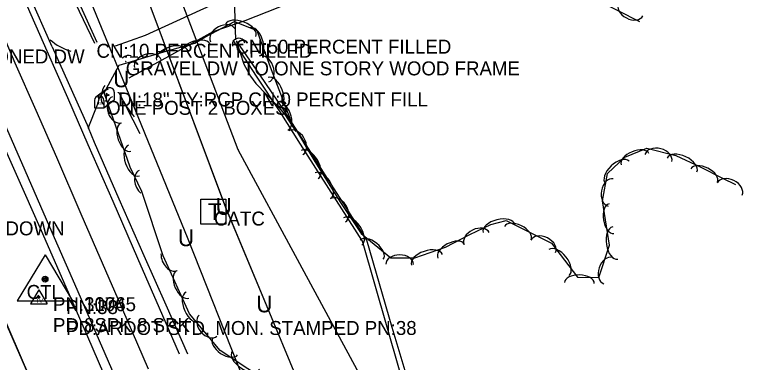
# Model space of a CAD drawing. Extents: x 954793 to 988390, y 1867850 to 1924428.
# Drawn here: x 964997.6 to 965258.9, y 1899641 to 1899765.7 of the extents above; entities that cross this region are included whole.
import ezdxf

# ---------------------------------------------------------------- set-up
doc = ezdxf.new("R2010")
doc.units = 0
for name, color, linetype in [('Default', 7, 'Continuous'), ('S_CROSS_DRAIN', 7, 'Continuous'), ('S_DITCHLINE', 7, 'Continuous'), ('S_DRG_PT_SYM', 7, 'Continuous'), ('S_DRIVEWAY', 7, 'Continuous'), ('S_EDGE_PAVEMENT', 7, 'Continuous'), ('S_FENCE', 7, 'Continuous'), ('S_FIBER_OPTIC_CABLE', 7, 'Continuous'), ('S_MAILBOX', 7, 'Continuous'), ('S_MAILBOX_ANNOT', 7, 'Continuous'), ('S_MSC_PT_SYM', 7, 'Continuous'), ('S_PAVEMENT_CROWN', 7, 'Continuous'), ('S_PRIMARY_CTL', 7, 'Continuous'), ('S_PRIMARY_CTL_ANNOT', 7, 'Continuous'), ('S_SECONDARY_CTL', 7, 'Continuous'), ('S_SECONDARY_CTL_ANNOT', 7, 'Continuous'), ('S_SHOULDER', 7, 'Continuous'), ('S_SIDE_DRAIN', 7, 'Continuous'), ('S_SIDE_DRAIN_ANNOT', 7, 'Continuous'), ('S_STREAM', 7, 'Continuous'), ('S_SURVEY_TEXT_ANNOT', 7, 'Continuous'), ('S_TELEPHONE_UTILITIES', 7, 'Continuous'), ('S_TELEPHONE_UTILITIES_ANNOT', 7, 'Continuous'), ('S_TREE', 7, 'Continuous'), ('S_UNDERGROUND_CABLE', 7, 'Continuous'), ('S_UTL_PT_SYM', 7, 'Continuous'), ('S_WATER_UTILITIES', 7, 'Continuous')]:
    doc.layers.add(name, color=color, linetype=linetype)

msp = doc.modelspace()

# ---------------------------------------------------------------- linework, layer by layer
at = {"layer": 'S_CROSS_DRAIN'}
msp.add_arc((965077.8, 1899754.9), 2.3, 13.2488, 193.578, dxfattribs=at)
at = {"layer": 'S_DITCHLINE'}
for points in [[(965026.32, 1899755.36), (965019.55, 1899769.53), (965012.77, 1899783.69), (965006, 1899797.85), (964999.22, 1899812.02), (964991.34, 1899825.84), (964983.45, 1899839.67), (964977.86, 1899852.94), (964972.26, 1899866.21), (964966.67, 1899879.48), (964961.07, 1899892.75), (964954.42, 1899908.66), (964947.77, 1899924.57), (964941.11, 1899940.47), (964934.46, 1899956.38), (964927.09, 1899973.92), (964919.72, 1899991.46), (964912.35, 1900008.99), (964904.98, 1900026.53), (964899.8, 1900040.82)], [(965027.15, 1899755.7), (965020.67, 1899769.95), (965014.19, 1899784.21), (965007.71, 1899798.46), (965001.23, 1899812.71), (964993.53, 1899826.7), (964985.84, 1899840.69), (964979.82, 1899853.82), (964973.81, 1899866.96), (964967.79, 1899880.09), (964961.78, 1899893.22), (964955.75, 1899909.26), (964949.73, 1899925.3), (964943.7, 1899941.34), (964937.68, 1899957.38), (964929.93, 1899974.73), (964922.17, 1899992.09), (964914.42, 1900009.44), (964906.67, 1900026.79), (964900.96, 1900041.28)], [(965135.42, 1899638.19), (965131, 1899653.62), (965126.58, 1899669.04), (965122.17, 1899684.46), (965114.78, 1899696.04), (965107.39, 1899707.62), (965100, 1899719.19), (965092.61, 1899730.77), (965084.22, 1899743.62), (965075.84, 1899756.46)], [(965137.39, 1899637.95), (965132.82, 1899653.57), (965128.26, 1899669.19), (965123.69, 1899684.81), (965116.25, 1899696.52), (965108.8, 1899708.23), (965101.36, 1899719.93), (965093.91, 1899731.64), (965085.46, 1899743.95), (965077.01, 1899756.26)], [(965034.84, 1899737.7), (965042.43, 1899723.09)]]:
    msp.add_lwpolyline(points, dxfattribs=at)
at = {"layer": 'S_DRG_PT_SYM'}
for points in [[(965026.89, 1899755.2), (965026.89, 1899755.25), (965026.89, 1899755.2), (965026.84, 1899755.2), (965026.89, 1899755.2), (965026.89, 1899755.15), (965026.89, 1899755.2), (965026.94, 1899755.2)], [(965076.66, 1899756.68), (965076.66, 1899756.73), (965076.66, 1899756.68), (965076.61, 1899756.68), (965076.66, 1899756.68), (965076.66, 1899756.63), (965076.66, 1899756.68), (965076.71, 1899756.68)], [(965034.69, 1899737.77), (965034.69, 1899737.82), (965034.69, 1899737.77), (965034.64, 1899737.77), (965034.69, 1899737.77), (965034.69, 1899737.72), (965034.69, 1899737.77), (965034.74, 1899737.77)]]:
    msp.add_lwpolyline(points, dxfattribs=at)
at = {"layer": 'S_DRIVEWAY'}
for points in [[(965190.73, 1899821.69), (965178.72, 1899814.96), (965168.54, 1899808.89), (965152.66, 1899802.03), (965128.23, 1899793.11), (965102.33, 1899783.62), (965081.71, 1899775.32), (965063.92, 1899767.13), (965044.28, 1899758.24), (965033.55, 1899754.37)], [(965038.61, 1899743.06), (965052.77, 1899750.75), (965068.67, 1899759.66), (965080.14, 1899763.52), (965091.95, 1899768.23), (965111.63, 1899776.26), (965138.64, 1899786.44), (965159.54, 1899793.86), (965177.42, 1899799.22), (965190.78, 1899800.84), (965203.59, 1899801.64)], [(965023.92, 1899725.01), (965027.38, 1899733.67)]]:
    msp.add_lwpolyline(points, dxfattribs=at)
for centre, major_axis, ratio, start_param, end_param in [((965023.42, 1899771.34), (16.15, 11.3), 0.985152, 3.375217, 3.811791), ((965033.7, 1899733.18), (0.99, -6.3), 0.993311, 3.413743, 4.47993)]:
    msp.add_ellipse(centre, major_axis=major_axis, ratio=ratio, start_param=start_param, end_param=end_param, dxfattribs=at)
at = {"layer": 'S_EDGE_PAVEMENT'}
for points in [[(965034.41, 1899633.87), (965026.77, 1899651.45), (965019.13, 1899669.03), (965010.21, 1899689.44), (965001.29, 1899709.85), (964993.95, 1899726.73), (964986.61, 1899743.6), (964978.51, 1899762.13), (964970.42, 1899780.65), (964962.5, 1899798.82), (964954.57, 1899816.98), (964945.65, 1899837.55), (964936.72, 1899858.12), (964928.96, 1899876), (964921.2, 1899893.88), (964912.27, 1899914.4), (964903.33, 1899934.92), (964895.65, 1899952.43)], [(965056.6, 1899643.95), (965049.43, 1899660.48), (965041.73, 1899678.21), (965032.84, 1899698.63), (965023.94, 1899719.05), (965016.6, 1899735.79), (965009.26, 1899752.54), (965000.91, 1899771.65), (964992.57, 1899790.77), (964984.95, 1899808.26), (964977.34, 1899825.76), (964968.39, 1899846.47), (964959.44, 1899867.18), (964951.66, 1899885.11), (964943.88, 1899903.04), (964934.93, 1899923.61), (964925.98, 1899944.18)]]:
    msp.add_lwpolyline(points, dxfattribs=at)
at = {"layer": 'S_FENCE'}
msp.add_line((965004.74, 1899631.67), (964978.21, 1899692.48), dxfattribs=at)
msp.add_lwpolyline([(965004.74, 1899631.67), (964995.05, 1899653.9)], dxfattribs=at)
at = {"layer": 'S_FIBER_OPTIC_CABLE'}
for p, q in [((965073.22, 1899696.48), (965037.96, 1899790.89)), ((965087.74, 1899661.5), (965073.22, 1899696.48)), ((965137.89, 1899541.6), (965087.74, 1899661.5))]:
    msp.add_line(p, q, dxfattribs=at)
at = {"layer": 'S_MAILBOX'}
for p, q in [((965026.7, 1899736.18), (965030.84, 1899739.29)), ((965030.32, 1899737.47), (965030.32, 1899734.76)), ((965033.27, 1899737.82), (965033.27, 1899735.1)), ((965026.15, 1899734.91), (965026.15, 1899732.2)), ((965029.47, 1899732.2), (965033.27, 1899735.1)), ((965029.47, 1899734.91), (965029.47, 1899732.2)), ((965026.15, 1899732.2), (965029.47, 1899732.2))]:
    msp.add_line(p, q, dxfattribs=at)
for points in [[(965027.33, 1899736.03), (965027.56, 1899735.89), (965027.56, 1899735.5), (965027.86, 1899735.5), (965027.86, 1899735.86), (965027.67, 1899736.11), (965027.33, 1899736.05)], [(965030.32, 1899737.47), (965031.43, 1899736.81), (965030.32, 1899736.46)]]:
    msp.add_lwpolyline(points, dxfattribs=at)
for centre, end in [((965031.61, 1899737.82), 117.5718), ((965027.81, 1899734.91), 180)]:
    msp.add_arc(centre, 1.66, 0, end, dxfattribs=at)
msp.add_ellipse((965030.32, 1899734.76), major_axis=(0.145, 0.132), ratio=0.564646, dxfattribs=at)
at = {"layer": 'S_MSC_PT_SYM'}
msp.add_lwpolyline([(965037.37, 1899748.9), (965037.37, 1899748.95), (965037.37, 1899748.9), (965037.32, 1899748.9), (965037.37, 1899748.9), (965037.37, 1899748.85), (965037.37, 1899748.9), (965037.42, 1899748.9)], dxfattribs=at)
at = {"layer": 'S_PAVEMENT_CROWN'}
msp.add_lwpolyline([(965045.56, 1899638.61), (965037.87, 1899656.22), (965030.19, 1899673.84), (965021.46, 1899694.12), (965012.73, 1899714.4), (965005.27, 1899731.31), (964997.81, 1899748.21), (964989.84, 1899766.64), (964981.86, 1899785.07), (964973.87, 1899803.37), (964965.89, 1899821.67), (964957.02, 1899842.07), (964948.15, 1899862.47), (964940.2, 1899881.32), (964932.26, 1899900.16), (964923.25, 1899920.03), (964914.24, 1899939.9)], dxfattribs=at)
at = {"layer": 'S_PRIMARY_CTL'}
for p, q in [((965008.46, 1899679.55), (964998.43, 1899663.04)), ((965008.46, 1899679.55), (965018.29, 1899663.04)), ((964998.43, 1899663.04), (965018.29, 1899663.04))]:
    msp.add_line(p, q, dxfattribs=at)
for radius in [1.04, 0.609, 0.344]:
    msp.add_circle((965008.46, 1899670.85), radius, dxfattribs=at)
at = {"layer": 'S_SECONDARY_CTL'}
for p, q in [((965006.3, 1899667), (965003.29, 1899662.05)), ((965006.3, 1899667), (965009.25, 1899662.05)), ((965003.29, 1899662.05), (965009.25, 1899662.05))]:
    msp.add_line(p, q, dxfattribs=at)
for radius in [0.311, 0.183, 0.103]:
    msp.add_circle((965006.3, 1899664.39), radius, dxfattribs=at)
at = {"layer": 'S_SHOULDER'}
msp.add_line((965011.03, 1899754.16), (965024.01, 1899725.04), dxfattribs=at)
for points in [[(965011.03, 1899754.16), (965002.84, 1899772.86), (964994.65, 1899791.56), (964987.01, 1899809.04), (964979.37, 1899826.51), (964970.32, 1899847.22), (964961.26, 1899867.93), (964953.37, 1899885.83), (964945.48, 1899903.72), (964936.59, 1899924.37), (964927.7, 1899945.01), (964920.2, 1899962.04), (964912.7, 1899979.08), (964903.65, 1900000.26), (964894.61, 1900021.44), (964885.7, 1900041.46), (964876.79, 1900061.49), (964869.66, 1900077.69), (964862.53, 1900093.89), (964862.02, 1900095.03)], [(965041.51, 1899609.64), (965040.62, 1899611.67), (965031.46, 1899632.5), (965023.76, 1899650.22), (965016.06, 1899667.95), (965007.17, 1899688.14), (964998.29, 1899708.33), (964990.56, 1899725.33), (964982.83, 1899742.34)], [(965059.65, 1899644), (965051.86, 1899661.5), (965043.96, 1899679.23), (965035.05, 1899699.55), (965026.15, 1899719.88), (965024.01, 1899725.04)]]:
    msp.add_lwpolyline(points, dxfattribs=at)
at = {"layer": 'S_SIDE_DRAIN'}
msp.add_line((965076.07, 1899774.81), (965076.66, 1899756.68), dxfattribs=at)
at = {"layer": 'S_STREAM'}
for points in [[(965077, 1899756.01), (965079.63, 1899747.92), (965082.09, 1899743.66), (965083.9, 1899741.04), (965091.46, 1899733.2), (965094.38, 1899729.87), (965098.24, 1899723.82)], [(965037.14, 1899733.31), (965040.33, 1899728.99)]]:
    msp.add_lwpolyline(points, dxfattribs=at)
at = {"layer": 'S_TELEPHONE_UTILITIES'}
msp.add_lwpolyline([(965064.25, 1899690.56), (965064.25, 1899699.56), (965073.25, 1899699.56), (965073.25, 1899690.56)], close=True, dxfattribs=at)
at = {"layer": 'S_TREE'}
for points in [[(965221.5, 1899763.12), (965206.2, 1899771.01), (965193.73, 1899776.5), (965186.26, 1899779.98), (965179.07, 1899780.87), (965166.6, 1899777.03), (965160.28, 1899774.45), (965158.42, 1899773.9), (965153.07, 1899772.43), (965145.89, 1899775.05), (965145.87, 1899780.41), (965152.63, 1899787.24), (965180.82, 1899805.67), (965187.67, 1899806.94), (965200.01, 1899805.17)], [(965091.02, 1899632.17), (965071.17, 1899645.31), (965060.19, 1899658.44), (965050.73, 1899679.19), (965043.07, 1899702.22), (965038.9, 1899710.97), (965029.66, 1899737.64), (965035.04, 1899747.5), (965050.96, 1899752.3), (965062.11, 1899755.45), (965065.64, 1899757.57), (965076.36, 1899763.17), (965084.34, 1899759.92), (965089.49, 1899745.96), (965096.7, 1899726.99), (965105.07, 1899713), (965114.04, 1899698.72), (965121.61, 1899687.24), (965132.27, 1899678.55), (965140.94, 1899678.51), (965151.86, 1899682.27), (965160.58, 1899686.88), (965168.12, 1899690.48), (965173.57, 1899691.82), (965189.78, 1899683.78), (965199.19, 1899671.62), (965206.79, 1899671.41), (965210.63, 1899683.02), (965208.1, 1899698.96), (965209.87, 1899708.67), (965216.06, 1899714.61), (965223.94, 1899717.84), (965234.37, 1899715.14), (965243.11, 1899711.09), (965251.08, 1899707.08), (965255.77, 1899704.76)]]:
    msp.add_lwpolyline(points, dxfattribs=at)
for centre, major_axis, ratio, start_param, end_param in [((965218.18, 1899767.5), (4.4, -2.27), 0.685311, 3.141593, 6.283185), ((965072.1, 1899758.26), (-4.39, -2.29), 0.685311, 3.141593, 6.283185), ((965078.54, 1899759.99), (-5.44, 2.21), 0.55008, 3.141593, 6.283185), ((965083.55, 1899755.93), (-1.85, 5.02), 0.540699, 3.141593, 6.283185), ((965054.02, 1899750.96), (-5.65, -1.6), 0.55008, 3.141593, 6.283185), ((965062.56, 1899753.37), (-5.14, -1.45), 0.540699, 3.141593, 6.283185), ((965045.25, 1899748.09), (-4.74, -1.43), 0.685311, 3.141593, 6.283185), ((965036.73, 1899746.18), (-2.56, -4.69), 0.540699, 3.141593, 4.099776), ((965086.87, 1899746.18), (-1.72, 4.65), 0.685311, 3.141593, 6.283185), ((965090.41, 1899737.59), (-2.09, 5.49), 0.55008, 3.141593, 6.283185), ((965032.48, 1899738.39), (-2.81, -5.15), 0.55008, 4.636383, 6.283185), ((965034.28, 1899731.58), (1.62, -4.68), 0.685311, 3.141593, 6.283185), ((965093.56, 1899729.3), (-1.9, 5), 0.540699, 3.141593, 6.283185), ((965037.41, 1899721.76), (1.75, -5.05), 0.540699, 3.141593, 6.283185), ((965098.27, 1899719.74), (-2.54, 4.25), 0.685311, 3.141593, 6.283185), ((965040.32, 1899713.38), (1.92, -5.54), 0.55008, 3.141593, 6.283185), ((965103.24, 1899711.93), (-3.01, 5.04), 0.55008, 3.141593, 6.283185), ((965228.1, 1899714.3), (-4.8, 1.24), 0.685311, 3.141593, 6.283185), ((965219.76, 1899713.84), (-4.95, -2.03), 0.540699, 3.141593, 6.283185), ((965236.56, 1899711.79), (-5.32, 2.47), 0.55008, 3.141593, 6.283185), ((965213.39, 1899709.11), (-4.23, -4.06), 0.55008, 3.141593, 6.283185), ((965244.51, 1899708.01), (-4.77, 2.41), 0.540699, 3.141593, 6.283185), ((965044.26, 1899705.27), (2.13, -4.47), 0.685311, 3.141593, 5.280714), ((965107.98, 1899704.38), (-2.84, 4.53), 0.540699, 3.141593, 6.283185), ((965253.63, 1899703.16), (-4.44, 2.19), 0.685311, 3.141593, 6.283185), ((965211.06, 1899701.93), (-0.89, -4.87), 0.685311, 3.141593, 6.283185), ((965113.31, 1899695.49), (-2.73, 4.14), 0.685311, 3.141593, 6.283185), ((965211.27, 1899692.52), (0.84, -5.28), 0.540699, 3.141593, 6.283185), ((965118.63, 1899687.91), (-3.23, 4.9), 0.55008, 3.141593, 6.283185), ((965171.03, 1899689.01), (-5.7, -1.4), 0.55008, 3.141593, 6.283185), ((965163.02, 1899685.4), (-4.47, -2.14), 0.685311, 3.141593, 6.283185), ((965177.76, 1899687.38), (-4.79, 2.38), 0.540699, 3.141593, 6.283185), ((965212.66, 1899683.76), (0.92, -5.8), 0.55008, 3.141593, 6.283185), ((965186.87, 1899682.57), (-4.44, 2.2), 0.685311, 3.141593, 6.283185), ((965125.44, 1899681.39), (-4.14, 3.38), 0.540699, 3.141593, 6.283185), ((965153.85, 1899680.92), (-4.73, -2.5), 0.540699, 3.141593, 6.283185), ((965145.23, 1899677.75), (-5.55, -1.91), 0.55008, 3.141593, 6.283185), ((965192.51, 1899676.8), (-3.59, 4.64), 0.55008, 3.141593, 6.283185), ((965053.69, 1899678.44), (2.06, -4.51), 0.685311, 4.097586, 6.283185), ((965135.48, 1899676.16), (-4.96, 0.02), 0.685311, 3.141593, 6.283185), ((965210.11, 1899673.88), (-1.56, -4.7), 0.685311, 3.141593, 6.283185), ((965057.73, 1899668.95), (2.22, -4.86), 0.540699, 3.141593, 6.283185), ((965199.81, 1899669.48), (-5.34, 0.15), 0.540699, 3.141593, 6.283185), ((965061.41, 1899660.89), (2.44, -5.34), 0.55008, 3.141593, 6.283185), ((965066.86, 1899654.18), (3.18, -3.8), 0.685311, 3.141593, 6.283185), ((965072.95, 1899646.67), (4.46, -2.95), 0.540699, 3.141593, 6.283185), ((965080.34, 1899641.78), (4.89, -3.24), 0.55008, 3.141593, 6.283185)]:
    msp.add_ellipse(centre, major_axis=major_axis, ratio=ratio, start_param=start_param, end_param=end_param, dxfattribs=at)
at = {"layer": 'S_UNDERGROUND_CABLE'}
for p, q in [((965073.2, 1899696.47), (965037.94, 1899790.83)), ((965036.5, 1899742.18), (965023.84, 1899773.05)), ((965059.69, 1899685.22), (965036.5, 1899742.18)), ((965087.75, 1899661.5), (965073.2, 1899696.47)), ((965085.76, 1899619.56), (965059.69, 1899685.22)), ((965137.89, 1899541.6), (965087.75, 1899661.5))]:
    msp.add_line(p, q, dxfattribs=at)
at = {"layer": 'S_UTL_PT_SYM'}
for points in [[(965077.66, 1899717.22), (965077.66, 1899717.27), (965077.66, 1899717.22), (965077.61, 1899717.22), (965077.66, 1899717.22), (965077.66, 1899717.17), (965077.66, 1899717.22), (965077.71, 1899717.22)], [(965073.22, 1899696.48), (965073.22, 1899696.53), (965073.22, 1899696.48), (965073.17, 1899696.48), (965073.22, 1899696.48), (965073.22, 1899696.43), (965073.22, 1899696.48), (965073.27, 1899696.48)], [(965087.74, 1899661.5), (965087.74, 1899661.55), (965087.74, 1899661.5), (965087.69, 1899661.5), (965087.74, 1899661.5), (965087.74, 1899661.45), (965087.74, 1899661.5), (965087.79, 1899661.5)]]:
    msp.add_lwpolyline(points, dxfattribs=at)
at = {"layer": 'S_WATER_UTILITIES'}
for p, q in [((965077.66, 1899717.22), (965051.15, 1899786.88)), ((965121.83, 1899635.46), (965077.66, 1899717.22))]:
    msp.add_line(p, q, dxfattribs=at)

# ---------------------------------------------------------------- texts
at = {"layer": 'Default'}
for p in [(965032.87, 1899739.63), (965069.57, 1899693.92), (965056.06, 1899682.67), (965084.12, 1899658.96)]:
    msp.add_text('U', height=6, rotation=360, dxfattribs=at).set_placement(p)
at = {"layer": 'S_MAILBOX'}
msp.add_text('US', height=0.96, rotation=360, dxfattribs=at).set_placement((965026.91, 1899733.39))
at = {"layer": 'S_MAILBOX_ANNOT'}
msp.add_text('ONE POST 2 BOXES', height=5, dxfattribs=at).set_placement((965030.32, 1899729.76))
at = {"layer": 'S_PRIMARY_CTL'}
msp.add_text('CTL', height=5, rotation=360, dxfattribs=at).set_placement((965001.88, 1899663.77))
at = {"layer": 'S_PRIMARY_CTL_ANNOT'}
for s, p in [('PN:38', (965015.96, 1899658.35)), ('PD:ARDOT STD. MON. STAMPED PN:38', (965015.96, 1899650.85))]:
    msp.add_text(s, height=5, dxfattribs=at).set_placement(p)
at = {"layer": 'S_SECONDARY_CTL'}
msp.add_text('TV', height=1.5, rotation=360, dxfattribs=at).set_placement((965005.09, 1899662.38))
at = {"layer": 'S_SECONDARY_CTL_ANNOT'}
for s, p in [('PN:1176', (965011.3, 1899659.39)), ('PN:30045', (965011.3, 1899659.39)), ('PD:8SPK 8 SPK', (965011.3, 1899651.89)), ('PD:8SPK 8 SPK', (965011.3, 1899651.89))]:
    msp.add_text(s, height=5, dxfattribs=at).set_placement(p)
at = {"layer": 'S_SIDE_DRAIN_ANNOT'}
for s, p in [('CN:10 PERCENT FILLED', (965026.89, 1899750.2)), ('CN:50 PERCENT FILLED', (965076.66, 1899751.68)), ('DI:18" TY:RCP CN:0 PERCENT FILL', (965034.69, 1899732.77))]:
    msp.add_text(s, height=5, dxfattribs=at).set_placement(p)
at = {"layer": 'S_SURVEY_TEXT_ANNOT'}
for s, p in [('ABANDONED DW', (964967.28, 1899748.17)), ('GRAVEL DW TO ONE STORY WOOD FRAME', (965037.37, 1899743.9)), ('BU WAS TORE DOWN', (964945.63, 1899686.56))]:
    msp.add_text(s, height=5, dxfattribs=at).set_placement(p)
at = {"layer": 'S_TELEPHONE_UTILITIES'}
msp.add_text('T', height=6, rotation=360, dxfattribs=at).set_placement((965066.81, 1899692.06))
at = {"layer": 'S_TELEPHONE_UTILITIES_ANNOT'}
msp.add_text('CATC', height=5, dxfattribs=at).set_placement((965068.98, 1899690.07))

doc.saveas('drawing.dxf')
